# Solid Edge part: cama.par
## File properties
Author: ion
Template: Iso Part.par
Last saved by: ion
Revision: 1
Application: Solid Edge
Accuracy: 0,990
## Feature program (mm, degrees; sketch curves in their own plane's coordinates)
sketch for "unnamed Protrusion 1" #1 plane through (0, 0, 0) normal (0, -1, 0) x-axis (1, 0, 0)
sketch for "unnamed Protrusion 1" #2 plane through (0, 0, 0) normal (0, -1, 0) x-axis (1, 0, 0)
  circle centre (0, 0) radius 5
extrude "unnamed Protrusion 1" add finite 40 along -normal
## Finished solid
Body 1: solid body, 4 faces, 4 edges, 0 vertices.
  Faces by surface: plane 2, cylinder 1, swept 1
  Edges by curve: circle 2, ellipse 2
Bounding box of the edges (mm; curved faces can reach further): 20.000 x 40.000 x 30.000, from (-10, 0, -15) to (10, 40, 15).
Cylindrical faces by radius (mm): R5 x1
Planar faces by outward normal: +y 1, -y 1
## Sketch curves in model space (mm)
circle centre (0, 0, 0) radius 5
ellipse centre (0, 0, 0) radii 15, 10
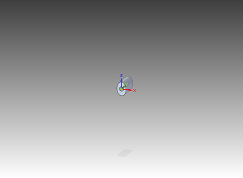
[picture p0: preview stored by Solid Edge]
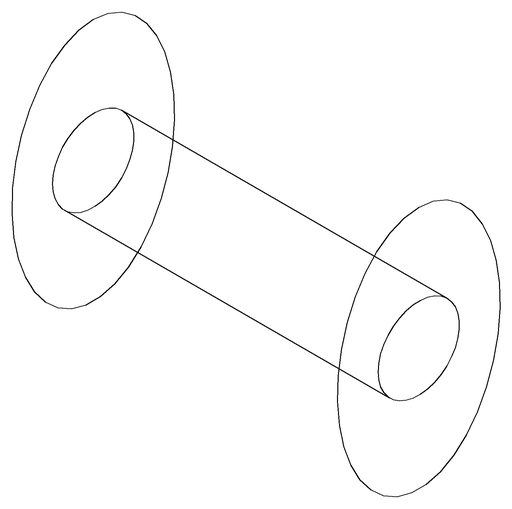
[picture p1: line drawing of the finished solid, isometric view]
